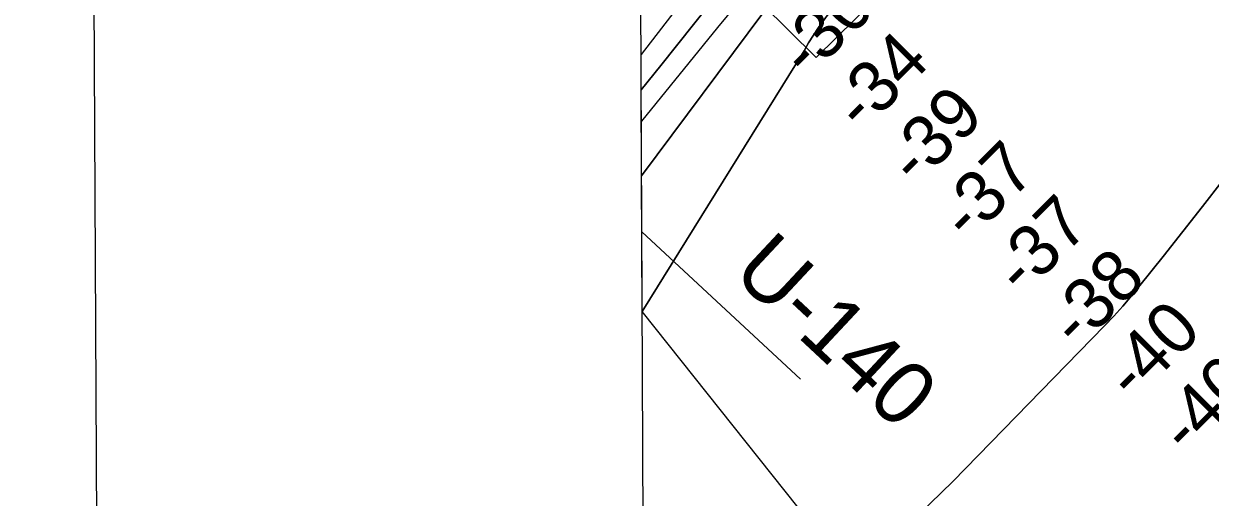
# Model space of a CAD drawing. Extents: x 3445503 to 3483459, y 540493 to 566012.
# Drawn here: x 3448839 to 3450391, y 545987 to 546607 of the extents above; entities that cross this region are included whole.
import ezdxf

# ---------------------------------------------------------------- set-up
doc = ezdxf.new("R2010")
doc.units = 0
for name, color, linetype in [('V-ANNO-SYMB', 7, 'Continuous'), ('V-GRID-FRAM', 7, 'Continuous'), ('V-RIVR-RANG', 7, 'Continuous'), ('V-RIVR-RANG-IDEN', 7, 'Continuous'), ('V-RRAP-RVMT', 7, 'Continuous'), ('V-TOPO-DPTH', 7, 'Continuous'), ('V-TOPO-MINR', 7, 'Continuous')]:
    doc.layers.add(name, color=color, linetype=linetype)

msp = doc.modelspace()

# ---------------------------------------------------------------- linework, layer by layer
at = {"layer": 'V-ANNO-SYMB'}
msp.add_lwpolyline([(3448956, 541715), (3482038.7, 541883.4), (3481922.1, 564799.7), (3448839.3, 564631.3), (3448956, 541715)], dxfattribs=at)
at = {"layer": 'V-GRID-FRAM'}
msp.add_lwpolyline([(3449565.1, 564068.2), (3481202, 564229.3), (3481302.5, 546046.4), (3449649.7, 545885.3), (3449565.1, 564068.2)], dxfattribs=at)
at = {"layer": 'V-RIVR-RANG'}
msp.add_line((3449647.6, 546334.5), (3449854.9, 546141.9), dxfattribs=at)
at = {"layer": 'V-RRAP-RVMT'}
msp.add_lwpolyline([(3449663.5, 546773.3), (3449875.7, 546562.7), (3449979.5, 546665.4), (3449992.8, 546651.6), (3450089.9, 546749.5), (3450078.9, 546761.5), (3450169.8, 546858.3), (3450168.7, 546859.4), (3450347.3, 547047.8), (3450345.7, 547049.4), (3450645.1, 547352.7), (3450640.5, 547357.3), (3450707, 547424.7)], dxfattribs=at)
at = {"layer": 'V-TOPO-DPTH'}
msp.add_line((3449921.6, 545886.6), (3449648.1, 546230.3), dxfattribs=at)
for points in [[(3450731, 547649.6), (3450373.4, 547278.8), (3450353.8, 547258.3), (3450334.2, 547237.7), (3450314.7, 547217), (3450295.4, 547196.1), (3450276.2, 547175.1), (3450257.2, 547154), (3450238.5, 547132.7), (3450219.8, 547111.2), (3449961.3, 546809.2), (3449941.6, 546786.2), (3449922.1, 546763.1), (3449902.6, 546739.9), (3449883.3, 546716.7), (3449864, 546693.3), (3449844.9, 546669.9), (3449826, 546646.3), (3449807.1, 546622.6), (3449647.3, 546407.9), (3449646.8, 546520.4)], [(3449647.3, 546407.9), (3449807.1, 546622.6), (3449826, 546646.3), (3449844.9, 546669.9), (3449864, 546693.3), (3449883.3, 546716.7), (3449902.6, 546739.9), (3449922.1, 546763.1), (3449941.6, 546786.2), (3449961.3, 546809.2), (3450219.8, 547111.2), (3450238.5, 547132.7), (3450257.2, 547154), (3450276.2, 547175.1), (3450295.4, 547196.1), (3450314.7, 547217), (3450334.2, 547237.7), (3450353.8, 547258.3), (3450373.4, 547278.8), (3450731, 547649.6)], [(3449646.8, 546520.4), (3449672.3, 546552.3), (3449715.3, 546606.1), (3449776.7, 546683.4), (3449788.9, 546698.6), (3449801.2, 546713.7), (3449813.6, 546728.7), (3449826.1, 546743.6), (3449929.2, 546864.8), (3449976.8, 546920.2), (3450024.7, 546975.2), (3450073.3, 547029.8), (3450122.2, 547084), (3450192.7, 547161.2), (3450206.7, 547176.5), (3450220.7, 547191.9), (3450234.8, 547207.2), (3450248.8, 547222.5), (3450587.9, 547592.4)], [(3449646.8, 546520.4), (3449672.3, 546552.3), (3449715.3, 546606.1), (3449776.7, 546683.4), (3449788.9, 546698.6), (3449801.2, 546713.7), (3449813.6, 546728.7), (3449826.1, 546743.6), (3449929.2, 546864.8), (3449976.8, 546920.2), (3450024.7, 546975.2), (3450073.3, 547029.8), (3450122.2, 547084), (3450192.7, 547161.2), (3450206.7, 547176.5), (3450220.7, 547191.9), (3450234.8, 547207.2), (3450248.8, 547222.5), (3450587.9, 547592.4)], [(3450862.6, 547442), (3450319.3, 547114.2), (3450313.2, 547108.2), (3450307.2, 547102.1), (3450301.3, 547095.8), (3450295.5, 547089.5), (3450268.4, 547059.4), (3450249.2, 547038), (3450230.1, 547016.4), (3450211.2, 546994.6), (3450192.5, 546972.8), (3449898.6, 546628.3), (3449895.8, 546624.9), (3449893.1, 546621.6), (3449890.4, 546618.2), (3449887.8, 546614.7), (3449878.7, 546602.2), (3449871.9, 546592.2), (3449865.6, 546582), (3449860, 546571.4), (3449648.1, 546230.3), (3449647.3, 546407.9)], [(3449648.1, 546230.3), (3449860, 546571.4), (3449865.6, 546582), (3449871.9, 546592.2), (3449878.7, 546602.2), (3449887.8, 546614.7), (3449890.4, 546618.2), (3449893.1, 546621.6), (3449895.8, 546624.9), (3449898.6, 546628.3), (3450192.5, 546972.8), (3450211.2, 546994.6), (3450230.1, 547016.4), (3450249.2, 547038), (3450268.4, 547059.4), (3450295.5, 547089.5), (3450301.3, 547095.8), (3450307.2, 547102.1), (3450313.2, 547108.2), (3450319.3, 547114.2), (3450862.6, 547442)], [(3450406.4, 546401), (3450380.9, 546367.9), (3450355.2, 546335), (3450329.2, 546302.2), (3450299, 546264.3), (3450287.8, 546250.7), (3450276.5, 546237.4), (3450264.7, 546224.5), (3450252.7, 546211.7), (3450054.5, 546007.9), (3449995.4, 545950.9)], [(3449995.4, 545950.9), (3450054.5, 546007.9), (3450252.7, 546211.7), (3450264.7, 546224.5), (3450276.5, 546237.4), (3450287.8, 546250.7), (3450299, 546264.3), (3450329.2, 546302.2), (3450355.2, 546335), (3450380.9, 546367.9), (3450406.4, 546401)]]:
    msp.add_lwpolyline(points, dxfattribs=at)
at = {"layer": 'V-TOPO-MINR'}
for points in [[(3450731, 547649.6), (3450373.4, 547278.8), (3450353.8, 547258.3), (3450334.2, 547237.7), (3450314.7, 547217), (3450295.4, 547196.1), (3450276.2, 547175.1), (3450257.2, 547154), (3450238.5, 547132.7), (3450219.8, 547111.2), (3449961.3, 546809.2), (3449941.6, 546786.2), (3449922.1, 546763.1), (3449902.6, 546739.9), (3449883.3, 546716.7), (3449864, 546693.3), (3449844.9, 546669.9), (3449826, 546646.3), (3449807.1, 546622.6), (3449647.3, 546407.9)], [(3450587.9, 547592.4), (3450248.8, 547222.5), (3450234.8, 547207.2), (3450220.7, 547191.9), (3450206.7, 547176.5), (3450192.7, 547161.2), (3450122.2, 547084), (3450073.3, 547029.8), (3450024.7, 546975.2), (3449976.8, 546920.2), (3449929.2, 546864.8), (3449826.1, 546743.6), (3449813.6, 546728.7), (3449801.2, 546713.7), (3449788.9, 546698.6), (3449776.7, 546683.4), (3449715.3, 546606.1), (3449672.3, 546552.3), (3449646.8, 546520.4)], [(3450862.6, 547442), (3450319.3, 547114.2), (3450313.2, 547108.2), (3450307.2, 547102.1), (3450301.3, 547095.8), (3450295.5, 547089.5), (3450268.4, 547059.4), (3450249.2, 547038), (3450230.1, 547016.4), (3450211.2, 546994.6), (3450192.5, 546972.8), (3449898.6, 546628.3), (3449895.8, 546624.9), (3449893.1, 546621.6), (3449890.4, 546618.2), (3449887.8, 546614.7), (3449878.7, 546602.2), (3449871.9, 546592.2), (3449865.6, 546582), (3449860, 546571.4), (3449648.1, 546230.3)], [(3450411.2, 547430.6), (3450351.6, 547365.9), (3450230.9, 547234.6), (3450218.4, 547221), (3450205.8, 547207.4), (3450193.2, 547193.8), (3450180.6, 547180.2), (3449936.8, 546918.2), (3449909.6, 546888.6), (3449882.7, 546858.8), (3449856.2, 546828.6), (3449829.9, 546798.2), (3449824.3, 546791.7), (3449801.2, 546764.2), (3449778.4, 546736.5), (3449756.1, 546708.5), (3449734, 546680.2), (3449646.6, 546566.6)], [(3450427.7, 547382.3), (3450249.3, 547189.8), (3450242.8, 547182.7), (3450236.3, 547175.7), (3450229.9, 547168.6), (3450223.5, 547161.5), (3450193.7, 547128.3), (3450172.5, 547104.5), (3450151.4, 547080.6), (3450130.6, 547056.6), (3450109.8, 547032.4), (3449827.8, 546701), (3449824.6, 546697.2), (3449821.4, 546693.3), (3449818.3, 546689.5), (3449815.1, 546685.7), (3449796.5, 546662.9), (3449784, 546647.7), (3449771.5, 546632.5), (3449759.1, 546617.2), (3449746.7, 546602), (3449647, 546479.4)], [(3449995.4, 545950.9), (3450054.5, 546007.9), (3450252.7, 546211.7), (3450264.7, 546224.5), (3450276.5, 546237.4), (3450287.8, 546250.7), (3450299, 546264.3), (3450329.2, 546302.2), (3450355.2, 546335), (3450380.9, 546367.9), (3450406.4, 546401)]]:
    msp.add_lwpolyline(points, dxfattribs=at)

# ---------------------------------------------------------------- texts
at = {"layer": 'V-RIVR-RANG'}
for s, p in [('-30', (3449864.3, 546533.2)), ('-34', (3449935.7, 546463.2)), ('-39', (3450006.4, 546392.4)), ('-37', (3450075, 546319.6)), ('-37', (3450145.6, 546248.8)), ('-38', (3450217.8, 546179.6)), ('-40', (3450290.8, 546111.2)), ('-40', (3450361.5, 546040.4))]:
    msp.add_text(s, height=67, rotation=45.0908, dxfattribs=at).set_placement(p)
at = {"layer": 'V-RIVR-RANG-IDEN'}
msp.add_text('U-140', height=83, rotation=316.9593, dxfattribs=at).set_placement((3449763.4, 546278.8))

doc.saveas('drawing.dxf')
